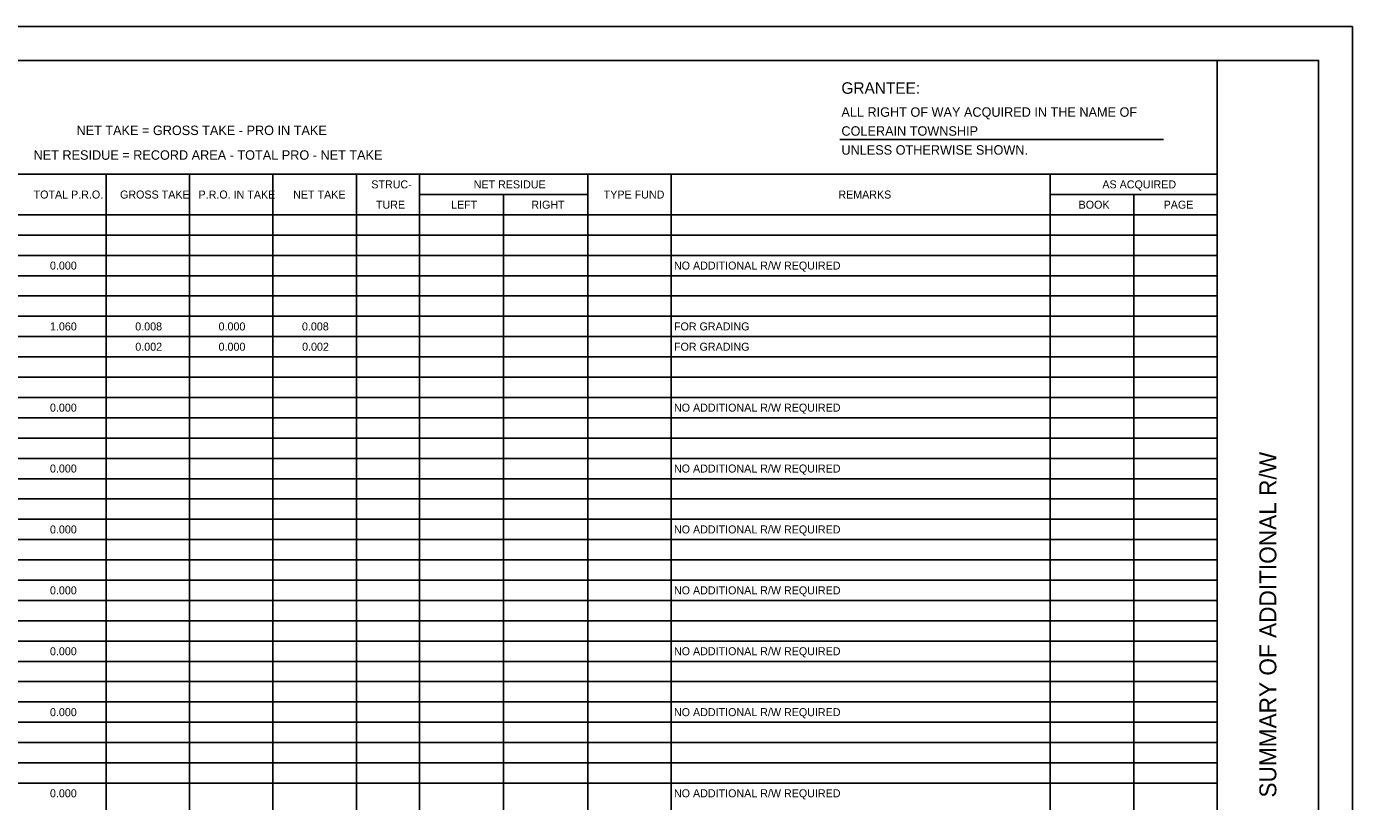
# Model space of a CAD drawing. Extents: x 0 to 34, y 0 to 22.
# Drawn here: x 14.41 to 34, y 10.55 to 22 of the extents above; entities that cross this region are included whole.
import ezdxf

# ---------------------------------------------------------------- set-up
doc = ezdxf.new("R2010")
doc.units = 0
for name, color, linetype in [('SH_Border', 7, 'Continuous'), ('SH_Cut_Line', 7, 'Continuous'), ('SH_Data', 7, 'Continuous'), ('SH_Text', 7, 'Continuous'), ('SN_P_Truss_Overhead', 7, 'Continuous')]:
    doc.layers.add(name, color=color, linetype=linetype)

msp = doc.modelspace()

# ---------------------------------------------------------------- linework, layer by layer
at = {"layer": 'SH_Border'}
msp.add_line((32, 0.5), (32, 21.5), dxfattribs=at)
msp.add_lwpolyline([(1.5, 21.5), (33.5, 21.5), (33.5, 0.5), (1.5, 0.5)], close=True, dxfattribs=at)
at = {"layer": 'SH_Cut_Line'}
msp.add_lwpolyline([(0, 0), (34, 0), (34, 22), (0, 22)], close=True, dxfattribs=at)
at = {"layer": 'SH_Text'}
msp.add_line((26.428, 20.33), (31.208, 20.33), dxfattribs=at)
at = {"layer": 'SN_P_Truss_Overhead'}
for p, q in [((1.501, 19.817), (32, 19.817)), ((15.588, 19.817), (15.588, 3.02)), ((16.82, 19.817), (16.82, 3.02)), ((18.052, 19.817), (18.052, 3.02)), ((19.284, 19.817), (19.284, 3.02)), ((20.216, 19.817), (20.216, 3.02)), ((22.701, 19.817), (22.701, 3.02)), ((23.933, 19.817), (23.933, 3.02)), ((29.536, 19.817), (29.536, 3.02)), ((32, 19.817), (32, 3.02)), ((20.216, 19.517), (22.701, 19.517)), ((21.459, 19.517), (21.459, 3.02)), ((29.536, 19.517), (32, 19.517)), ((30.768, 19.517), (30.768, 3.02)), ((1.501, 19.217), (32, 19.217)), ((1.501, 18.918), (32, 18.918)), ((1.501, 18.618), (32, 18.618)), ((1.501, 18.318), (32, 18.318)), ((1.501, 18.018), (32, 18.018)), ((1.501, 17.718), (32, 17.718)), ((1.501, 17.418), (32, 17.418)), ((1.501, 17.118), (32, 17.118)), ((1.501, 16.818), (32, 16.818)), ((1.501, 16.518), (32, 16.518)), ((1.501, 16.218), (32, 16.218)), ((1.501, 15.918), (32, 15.918)), ((1.501, 15.618), (32, 15.618)), ((1.501, 15.318), (32, 15.318)), ((1.501, 15.018), (32, 15.018)), ((1.501, 14.718), (32, 14.718)), ((1.501, 14.418), (32, 14.418)), ((1.501, 14.118), (32, 14.118)), ((1.501, 13.818), (32, 13.818)), ((1.501, 13.518), (32, 13.518)), ((1.501, 13.218), (32, 13.218)), ((1.501, 12.918), (32, 12.918)), ((1.501, 12.619), (32, 12.619)), ((1.501, 12.319), (32, 12.319)), ((1.501, 12.019), (32, 12.019)), ((1.501, 11.719), (32, 11.719)), ((1.501, 11.419), (32, 11.419)), ((1.501, 11.119), (32, 11.119)), ((1.501, 10.819), (32, 10.819))]:
    msp.add_line(p, q, dxfattribs=at)

# ---------------------------------------------------------------- texts
at = {"layer": 'SH_Data'}
msp.add_text('SUMMARY OF ADDITIONAL R/W', height=0.25, rotation=90, dxfattribs=at).set_placement((32.875, 10.606))
at = {"layer": 'SH_Text'}
for s, height, p in [('GRANTEE:', 0.17, (26.45, 21.006)), ('ALL RIGHT OF WAY ACQUIRED IN THE NAME OF', 0.14, (26.45, 20.666)), ('NET TAKE = GROSS TAKE - PRO IN TAKE', 0.14, (15.149, 20.396)), ('COLERAIN TOWNSHIP', 0.14, (26.45, 20.386)), ('UNLESS OTHERWISE SHOWN.', 0.14, (26.45, 20.106)), ('NET RESIDUE = RECORD AREA - TOTAL PRO - NET TAKE', 0.14, (14.515, 20.031))]:
    msp.add_text(s, height=height, dxfattribs=at).set_placement(p)
at = {"layer": 'SN_P_Truss_Overhead'}
for s, height, p in [('STRUC-', 0.1183, (19.504, 19.608)), ('NET RESIDUE', 0.11827, (21.017, 19.608)), ('AS ACQUIRED', 0.11827, (30.305, 19.608)), ('TOTAL P.R.O.', 0.11827, (14.515, 19.458)), ('GROSS TAKE', 0.1183, (15.792, 19.458)), ('P.R.O. IN TAKE', 0.11827, (16.952, 19.458)), ('NET TAKE', 0.1183, (18.35, 19.458)), ('TURE', 0.1183, (19.573, 19.308)), ('LEFT', 0.1183, (20.683, 19.308)), ('RIGHT', 0.1183, (21.868, 19.308)), ('TYPE FUND', 0.1183, (22.938, 19.458)), ('REMARKS', 0.1183, (26.404, 19.458)), ('BOOK', 0.1183, (29.954, 19.308)), ('PAGE', 0.1183, (31.21, 19.308)), ('0.000', 0.1183, (14.757, 18.408)), ('NO ADDITIONAL R/W REQUIRED', 0.11827, (23.976, 18.408)), ('1.060', 0.1183, (14.757, 17.509)), ('0.008', 0.1183, (16.017, 17.509)), ('0.000', 0.1183, (17.248, 17.509)), ('0.008', 0.1183, (18.48, 17.509)), ('FOR GRADING', 0.11827, (23.976, 17.509)), ('0.002', 0.1183, (16.018, 17.209)), ('0.000', 0.1183, (17.248, 17.209)), ('0.002', 0.1183, (18.482, 17.209)), ('FOR GRADING', 0.11827, (23.976, 17.209)), ('0.000', 0.1183, (14.757, 16.309)), ('NO ADDITIONAL R/W REQUIRED', 0.11827, (23.976, 16.309)), ('0.000', 0.1183, (14.757, 15.409)), ('NO ADDITIONAL R/W REQUIRED', 0.11827, (23.976, 15.409)), ('0.000', 0.1183, (14.757, 14.509)), ('NO ADDITIONAL R/W REQUIRED', 0.11827, (23.976, 14.509)), ('0.000', 0.1183, (14.757, 13.609)), ('NO ADDITIONAL R/W REQUIRED', 0.11827, (23.976, 13.609)), ('0.000', 0.1183, (14.757, 12.709)), ('NO ADDITIONAL R/W REQUIRED', 0.11827, (23.976, 12.709)), ('0.000', 0.1183, (14.757, 11.809)), ('NO ADDITIONAL R/W REQUIRED', 0.11827, (23.976, 11.809)), ('0.000', 0.1183, (14.757, 10.61)), ('NO ADDITIONAL R/W REQUIRED', 0.11827, (23.976, 10.61))]:
    msp.add_text(s, height=height, dxfattribs=at).set_placement(p)

doc.saveas('drawing.dxf')
